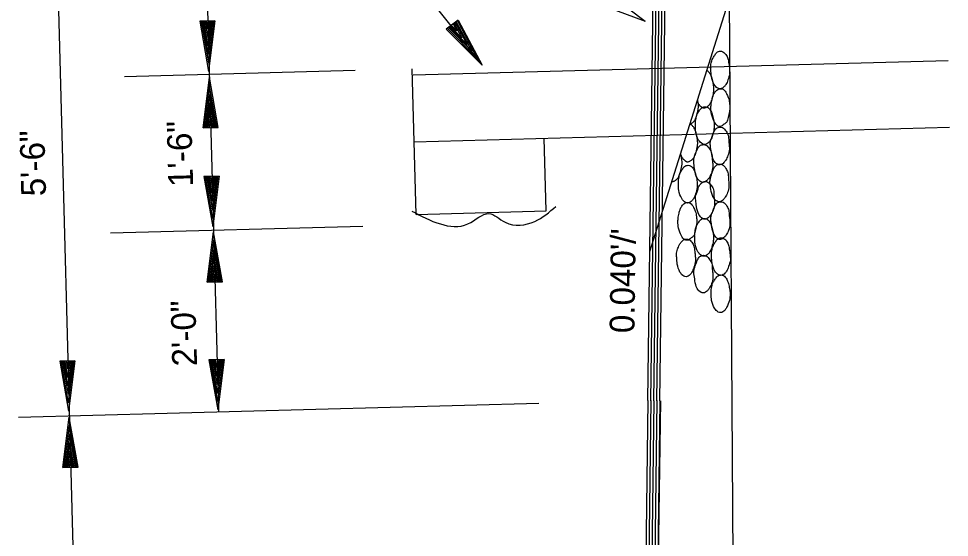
# Model space of a CAD drawing. Extents: x 1926836 to 1933254, y 596317 to 604524.
# Drawn here: x 1932874 to 1933102.1, y 600272.6 to 600399.7 of the extents above; entities that cross this region are included whole.
import ezdxf

# ---------------------------------------------------------------- set-up
doc = ezdxf.new("R2010")
doc.units = 0
doc.layers.add('Default', color=7, linetype='Continuous')

msp = doc.modelspace()

# ---------------------------------------------------------------- linework, layer by layer
at = {"layer": 'Default'}
for p, q in [((1933028.65, 600342.66), (1933087.62, 600529.6)), ((1933050.22, 600105.35), (1933047.48, 600498.79)), ((1932987.41, 600388.62), (1932933.19, 600456.49)), ((1933028.17, 600306.1), (1933029.94, 600440.85)), ((1933028.91, 600306.08), (1933030.68, 600440.83)), ((1933029.64, 600306.07), (1933031.42, 600440.83)), ((1933030.38, 600306.06), (1933032.16, 600440.81)), ((1933031.12, 600306.06), (1933032.89, 600440.81)), ((1932923, 600303.28), (1932919.41, 600436.93)), ((1932891.73, 600105.54), (1932882.86, 600435.95)), ((1933017.57, 600406.6), (1933027.52, 600399.09)), ((1933015.79, 600403.36), (1933027.52, 600399.09)), ((1932922.05, 600399.14), (1932918.34, 600399.04)), ((1932918.34, 600399.04), (1932920.51, 600386.77)), ((1932918.66, 600399.05), (1932920.46, 600388.84)), ((1932918.98, 600399.06), (1932920.4, 600390.95)), ((1932919.27, 600399.07), (1932920.34, 600393.02)), ((1932919.59, 600399.08), (1932920.29, 600395.08)), ((1932919.91, 600399.09), (1932920.23, 600397.15)), ((1932920.48, 600399.1), (1932920.23, 600397.15)), ((1932920.8, 600399.11), (1932920.29, 600395.08)), ((1932921.12, 600399.12), (1932920.34, 600393.02)), ((1932921.41, 600399.13), (1932920.4, 600390.95)), ((1932921.73, 600399.13), (1932920.46, 600388.84)), ((1932922.05, 600399.14), (1932920.51, 600386.77)), ((1932981.71, 600399.3), (1932978.76, 600397.13)), ((1932979, 600397.33), (1932986.36, 600389.95)), ((1932979.29, 600397.54), (1932985.04, 600391.71)), ((1932979.54, 600397.67), (1932983.84, 600393.34)), ((1932979.74, 600397.86), (1932982.61, 600394.98)), ((1932980.01, 600398.04), (1932981.38, 600396.66)), ((1932980.42, 600398.4), (1932981.38, 600396.66)), ((1932980.69, 600398.53), (1932982.61, 600394.98)), ((1932980.96, 600398.74), (1932983.84, 600393.34)), ((1932981.22, 600398.92), (1932985.04, 600391.71)), ((1932981.48, 600399.15), (1932986.36, 600389.95)), ((1932981.71, 600399.3), (1932987.56, 600388.3)), ((1932978.76, 600397.13), (1932987.56, 600388.3)), ((1932970.62, 600385.93), (1933101.74, 600389.44)), ((1932956.47, 600386.97), (1932899.92, 600385.45)), ((1932971.39, 600351.71), (1932970.44, 600387.35)), ((1932919.16, 600372.95), (1932920.7, 600385.32)), ((1932922.87, 600373.05), (1932920.7, 600385.32)), ((1932919.48, 600372.96), (1932920.75, 600383.26)), ((1932922.55, 600373.04), (1932920.75, 600383.26)), ((1932919.8, 600372.97), (1932920.81, 600381.14)), ((1932920.09, 600372.98), (1932920.87, 600379.08)), ((1932922.23, 600373.03), (1932920.81, 600381.14)), ((1932921.94, 600373.03), (1932920.87, 600379.08)), ((1932920.41, 600372.98), (1932920.92, 600377.01)), ((1932921.62, 600373.02), (1932920.92, 600377.01)), ((1932920.73, 600372.99), (1932920.98, 600374.94)), ((1932921.3, 600373.01), (1932920.98, 600374.94)), ((1932919.16, 600372.95), (1932922.87, 600373.05)), ((1932970.91, 600369.54), (1933102.05, 600373.06)), ((1933003.22, 600352.56), (1933002.74, 600370.4)), ((1932923.1, 600361.07), (1932919.38, 600360.97)), ((1932919.38, 600360.97), (1932921.56, 600348.7)), ((1932919.7, 600360.98), (1932921.5, 600350.76)), ((1932920.02, 600360.99), (1932921.45, 600352.88)), ((1932920.32, 600361), (1932921.39, 600354.95)), ((1932920.64, 600361), (1932921.34, 600357.01)), ((1932920.96, 600361.01), (1932921.28, 600359.08)), ((1932921.52, 600361.03), (1932921.28, 600359.08)), ((1932921.84, 600361.04), (1932921.34, 600357.01)), ((1932922.16, 600361.05), (1932921.39, 600354.95)), ((1932922.46, 600361.05), (1932921.45, 600352.88)), ((1932922.78, 600361.06), (1932921.5, 600350.76)), ((1932923.1, 600361.07), (1932921.56, 600348.7)), ((1932971.39, 600351.71), (1933003.22, 600352.56)), ((1932958.29, 600348.8), (1932896.45, 600347.14)), ((1932920.2, 600335.1), (1932921.74, 600347.47)), ((1932923.91, 600335.2), (1932921.74, 600347.47)), ((1932920.52, 600335.11), (1932921.79, 600345.41)), ((1932923.6, 600335.19), (1932921.79, 600345.41)), ((1932920.84, 600335.12), (1932921.85, 600343.29)), ((1932923.28, 600335.18), (1932921.85, 600343.29)), ((1932921.14, 600335.13), (1932921.91, 600341.23)), ((1932922.98, 600335.17), (1932921.91, 600341.23)), ((1932921.46, 600335.13), (1932921.96, 600339.16)), ((1932922.66, 600335.17), (1932921.96, 600339.16)), ((1932921.78, 600335.14), (1932922.02, 600337.09)), ((1932922.34, 600335.16), (1932922.02, 600337.09)), ((1932920.2, 600335.1), (1932923.91, 600335.2)), ((1932887.74, 600315.87), (1932884.02, 600315.77)), ((1932884.02, 600315.77), (1932886.2, 600303.5)), ((1932884.34, 600315.78), (1932886.14, 600305.56)), ((1932884.66, 600315.79), (1932886.09, 600307.68)), ((1932884.96, 600315.79), (1932886.03, 600309.74)), ((1932885.28, 600315.8), (1932885.97, 600311.81)), ((1932885.6, 600315.81), (1932885.92, 600313.87)), ((1932886.16, 600315.83), (1932885.92, 600313.87)), ((1932886.48, 600315.83), (1932885.97, 600311.81)), ((1932886.8, 600315.84), (1932886.03, 600309.74)), ((1932887.1, 600315.85), (1932886.09, 600307.68)), ((1932887.42, 600315.86), (1932886.14, 600305.56)), ((1932887.74, 600315.87), (1932886.2, 600303.5)), ((1932924.3, 600316.18), (1932920.59, 600316.09)), ((1932920.59, 600316.09), (1932922.76, 600303.81)), ((1932920.91, 600316.09), (1932922.71, 600305.88)), ((1932921.23, 600316.1), (1932922.65, 600307.99)), ((1932921.52, 600316.11), (1932922.6, 600310.06)), ((1932921.84, 600316.12), (1932922.54, 600312.13)), ((1932922.16, 600316.13), (1932922.49, 600314.19)), ((1932922.73, 600316.14), (1932922.49, 600314.19)), ((1932923.05, 600316.15), (1932922.54, 600312.13)), ((1932923.37, 600316.16), (1932922.6, 600310.06)), ((1932923.66, 600316.17), (1932922.65, 600307.99)), ((1932923.98, 600316.18), (1932922.71, 600305.88)), ((1932924.3, 600316.18), (1932922.76, 600303.81)), ((1933028.17, 600306.1), (1933026.23, 600158.37)), ((1933028.91, 600306.12), (1933026.96, 600158.39)), ((1933029.64, 600306.09), (1933027.7, 600158.36)), ((1933030.38, 600306.11), (1933028.44, 600158.38)), ((1933031.12, 600306.08), (1933029.18, 600158.35)), ((1933031.22, 600306.08), (1933029.28, 600158.45)), ((1933001.46, 600305.38), (1932873.96, 600301.96)), ((1932884.82, 600289.68), (1932886.36, 600302.05)), ((1932888.54, 600289.78), (1932886.36, 600302.05)), ((1932885.14, 600289.68), (1932886.42, 600299.98)), ((1932888.22, 600289.77), (1932886.42, 600299.98)), ((1932885.46, 600289.69), (1932886.47, 600297.87)), ((1932887.9, 600289.76), (1932886.47, 600297.87)), ((1932885.76, 600289.7), (1932886.53, 600295.8)), ((1932887.6, 600289.75), (1932886.53, 600295.8)), ((1932886.08, 600289.71), (1932886.58, 600293.73)), ((1932887.28, 600289.74), (1932886.58, 600293.73)), ((1932886.4, 600289.72), (1932886.64, 600291.67)), ((1932886.96, 600289.73), (1932886.64, 600291.67)), ((1932884.82, 600289.68), (1932888.54, 600289.78))]:
    msp.add_line(p, q, dxfattribs=at)
for points in [[(1933043.56, 600387.12), (1933043.75, 600385.5), (1933044.39, 600383.55), (1933045.3, 600382.64), (1933045.9, 600382.51), (1933046.87, 600383.02), (1933047.3, 600383.53), (1933047.76, 600384.67), (1933048.21, 600386.21), (1933048.19, 600387.05), (1933048.06, 600388.27), (1933047.82, 600389.65), (1933047.45, 600390.62), (1933046.54, 600391.58), (1933045.94, 600391.71), (1933045.07, 600391.39), (1933044.5, 600390.64), (1933044.07, 600389.89), (1933043.71, 600388.85), (1933043.58, 600388.15), (1933043.56, 600387.12)], [(1933040.25, 600379.42), (1933040.37, 600379.16), (1933040.44, 600379.03), (1933040.51, 600378.9), (1933040.71, 600378.61), (1933040.93, 600378.36), (1933041.18, 600378.14), (1933041.32, 600378.04), (1933041.48, 600377.94), (1933041.61, 600377.87), (1933041.75, 600377.82), (1933041.89, 600377.8), (1933041.95, 600377.8), (1933042.02, 600377.81), (1933042.29, 600377.89), (1933042.55, 600378.01), (1933042.8, 600378.18), (1933042.92, 600378.27), (1933043.04, 600378.38), (1933043.28, 600378.64), (1933043.47, 600378.93), (1933043.6, 600379.2), (1933043.73, 600379.47), (1933043.84, 600379.74), (1933043.93, 600380.02), (1933044.13, 600380.81), (1933044.28, 600381.61), (1933044.36, 600382.45), (1933044.35, 600382.6), (1933044.34, 600382.74), (1933044.31, 600383.04), (1933044.23, 600383.63), (1933044.17, 600383.96), (1933044.1, 600384.29), (1933044.03, 600384.62), (1933043.95, 600384.95), (1933043.86, 600385.21), (1933043.76, 600385.47), (1933043.65, 600385.72), (1933043.52, 600385.97), (1933043.37, 600386.24), (1933043.2, 600386.49), (1933042.98, 600386.72), (1933042.85, 600386.83), (1933042.78, 600386.88), (1933042.71, 600386.93), (1933042.63, 600386.98)], [(1933043.62, 600377.87), (1933043.76, 600376.25), (1933044.5, 600374.35), (1933045.31, 600373.38), (1933045.86, 600373.25), (1933046.88, 600373.82), (1933047.41, 600374.28), (1933047.87, 600375.47), (1933048.17, 600376.96), (1933048.25, 600377.79), (1933048.16, 600379.02), (1933047.88, 600380.39), (1933047.41, 600381.37), (1933046.6, 600382.38), (1933045.95, 600382.51), (1933045.08, 600382.19), (1933044.46, 600381.43), (1933044.13, 600380.69), (1933043.82, 600379.6), (1933043.69, 600378.9), (1933043.62, 600377.87)], [(1933038.47, 600373.79), (1933038.67, 600373.88), (1933038.87, 600373.99), (1933039.06, 600374.13), (1933039.24, 600374.29), (1933039.49, 600374.55), (1933039.67, 600374.84), (1933039.81, 600375.11), (1933039.93, 600375.38), (1933040.04, 600375.65), (1933040.13, 600375.94), (1933040.33, 600376.72), (1933040.49, 600377.52), (1933040.54, 600377.94), (1933040.56, 600378.15), (1933040.56, 600378.36), (1933040.52, 600378.95), (1933040.43, 600379.54), (1933040.38, 600379.84)], [(1933039.81, 600373.51), (1933039.91, 600371.89), (1933040.6, 600369.93), (1933041.56, 600368.98), (1933042.1, 600368.84), (1933043.12, 600369.41), (1933043.55, 600369.96), (1933044.01, 600371.06), (1933044.36, 600372.64), (1933044.44, 600373.48), (1933044.31, 600374.66), (1933044.03, 600375.98), (1933043.61, 600377.01), (1933042.79, 600377.97), (1933042.15, 600378.1), (1933041.27, 600377.78), (1933040.7, 600377.03), (1933040.28, 600376.33), (1933039.96, 600375.23), (1933039.83, 600374.54), (1933039.81, 600373.51)], [(1933036.16, 600366.47), (1933036.29, 600366.18), (1933036.41, 600365.94), (1933036.54, 600365.7), (1933036.73, 600365.41), (1933036.95, 600365.17), (1933037.2, 600364.95), (1933037.34, 600364.84), (1933037.5, 600364.74), (1933037.63, 600364.67), (1933037.77, 600364.62), (1933037.91, 600364.6), (1933037.98, 600364.6), (1933038.04, 600364.61), (1933038.31, 600364.69), (1933038.57, 600364.81), (1933038.82, 600364.98), (1933038.94, 600365.07), (1933039.06, 600365.18), (1933039.3, 600365.44), (1933039.49, 600365.73), (1933039.63, 600366), (1933039.75, 600366.27), (1933039.86, 600366.54), (1933039.95, 600366.83), (1933040.15, 600367.61), (1933040.3, 600368.41), (1933040.38, 600369.25), (1933040.37, 600369.4), (1933040.36, 600369.55), (1933040.34, 600369.84), (1933040.25, 600370.43), (1933040.19, 600370.76), (1933040.12, 600371.09), (1933040.05, 600371.42), (1933039.97, 600371.75), (1933039.89, 600372.01), (1933039.79, 600372.27), (1933039.67, 600372.52), (1933039.55, 600372.77), (1933039.39, 600373.05), (1933039.22, 600373.3), (1933039, 600373.53), (1933038.88, 600373.63), (1933038.73, 600373.73), (1933038.61, 600373.8), (1933038.49, 600373.84)], [(1933043.49, 600368.58), (1933043.73, 600366.87), (1933044.27, 600365.01), (1933045.24, 600364), (1933045.78, 600363.87), (1933046.8, 600364.44), (1933047.23, 600364.99), (1933047.79, 600366.14), (1933048.14, 600367.68), (1933048.12, 600368.46), (1933047.99, 600369.69), (1933047.85, 600371.11), (1933047.33, 600372.08), (1933046.47, 600373), (1933045.83, 600373.13), (1933044.95, 600372.81), (1933044.38, 600372.05), (1933044.1, 600371.36), (1933043.74, 600370.27), (1933043.51, 600369.62), (1933043.49, 600368.58)], [(1933039.42, 600364.19), (1933039.66, 600362.58), (1933040.21, 600360.67), (1933041.17, 600359.71), (1933041.71, 600359.58), (1933042.73, 600360.15), (1933043.16, 600360.7), (1933043.72, 600361.8), (1933044.07, 600363.38), (1933044.05, 600364.17), (1933043.92, 600365.4), (1933043.79, 600366.72), (1933043.26, 600367.79), (1933042.4, 600368.7), (1933041.76, 600368.83), (1933040.88, 600368.52), (1933040.31, 600367.76), (1933040.04, 600367.02), (1933039.57, 600365.97), (1933039.44, 600365.23), (1933039.42, 600364.19)], [(1933034.04, 600359.76), (1933034.08, 600359.75), (1933034.14, 600359.75), (1933034.21, 600359.76), (1933034.48, 600359.84), (1933034.74, 600359.97), (1933034.99, 600360.13), (1933035.11, 600360.23), (1933035.23, 600360.33), (1933035.47, 600360.59), (1933035.66, 600360.88), (1933035.79, 600361.15), (1933035.92, 600361.42), (1933036.03, 600361.7), (1933036.12, 600361.98), (1933036.32, 600362.77), (1933036.47, 600363.56), (1933036.53, 600363.98), (1933036.54, 600364.19), (1933036.55, 600364.4), (1933036.5, 600364.99), (1933036.46, 600365.29), (1933036.42, 600365.58), (1933036.32, 600366.1), (1933036.21, 600366.62)], [(1933035.65, 600359.18), (1933035.75, 600357.56), (1933036.49, 600355.61), (1933037.4, 600354.65), (1933037.99, 600354.51), (1933038.96, 600355.08), (1933039.39, 600355.64), (1933039.85, 600356.73), (1933040.25, 600358.32), (1933040.28, 600359.15), (1933040.15, 600360.33), (1933039.87, 600361.65), (1933039.45, 600362.68), (1933038.63, 600363.64), (1933038.04, 600363.77), (1933037.16, 600363.45), (1933036.59, 600362.7), (1933036.12, 600362), (1933035.8, 600360.9), (1933035.67, 600360.21), (1933035.65, 600359.18)], [(1933043.36, 600359.51), (1933043.61, 600357.84), (1933044.2, 600355.89), (1933045.11, 600354.93), (1933045.71, 600354.8), (1933046.67, 600355.36), (1933047.1, 600355.92), (1933047.71, 600357.06), (1933048.02, 600358.6), (1933047.99, 600359.39), (1933047.91, 600360.61), (1933047.73, 600361.99), (1933047.26, 600363.01), (1933046.35, 600363.92), (1933045.75, 600364.05), (1933044.87, 600363.73), (1933044.3, 600362.98), (1933043.98, 600362.23), (1933043.66, 600361.19), (1933043.48, 600360.54), (1933043.36, 600359.51)], [(1933039.89, 600355.25), (1933040.08, 600353.63), (1933040.68, 600351.67), (1933041.64, 600350.67), (1933042.19, 600350.53), (1933043.15, 600351.1), (1933043.58, 600351.65), (1933044.19, 600352.8), (1933044.5, 600354.34), (1933044.47, 600355.17), (1933044.34, 600356.35), (1933044.26, 600357.78), (1933043.74, 600358.75), (1933042.88, 600359.66), (1933042.23, 600359.79), (1933041.35, 600359.47), (1933040.78, 600358.77), (1933040.46, 600358.02), (1933040.14, 600356.98), (1933039.87, 600356.28), (1933039.89, 600355.25)], [(1933035.53, 600349.99), (1933035.67, 600348.37), (1933036.41, 600346.47), (1933037.23, 600345.51), (1933037.77, 600345.38), (1933038.79, 600345.95), (1933039.32, 600346.4), (1933039.78, 600347.6), (1933040.08, 600349.08), (1933040.16, 600349.92), (1933040.08, 600351.15), (1933039.79, 600352.52), (1933039.32, 600353.49), (1933038.51, 600354.5), (1933037.87, 600354.63), (1933036.99, 600354.32), (1933036.37, 600353.56), (1933036.04, 600352.81), (1933035.73, 600351.72), (1933035.6, 600351.03), (1933035.53, 600349.99)], [(1933043.62, 600350.25), (1933043.86, 600348.63), (1933044.45, 600346.68), (1933045.37, 600345.72), (1933045.96, 600345.59), (1933046.93, 600346.16), (1933047.36, 600346.71), (1933047.92, 600347.81), (1933048.27, 600349.34), (1933048.25, 600350.18), (1933048.12, 600351.41), (1933047.98, 600352.73), (1933047.51, 600353.75), (1933046.6, 600354.71), (1933046.01, 600354.84), (1933045.13, 600354.53), (1933044.56, 600353.77), (1933044.24, 600353.03), (1933043.87, 600351.93), (1933043.64, 600351.29), (1933043.62, 600350.25)], [(1932970.34, 600352.54), (1932977.34, 600349.38), (1932984.08, 600349.39), (1932989.21, 600351.94), (1932993.2, 600349.81), (1933000.46, 600350), (1933005.6, 600353.69)], [(1933039.64, 600346.14), (1933039.73, 600344.52), (1933040.42, 600342.57), (1933041.38, 600341.61), (1933041.93, 600341.48), (1933042.95, 600342.05), (1933043.37, 600342.6), (1933043.84, 600343.69), (1933044.19, 600345.28), (1933044.26, 600346.12), (1933044.13, 600347.3), (1933043.85, 600348.62), (1933043.43, 600349.64), (1933042.62, 600350.6), (1933041.97, 600350.73), (1933041.1, 600350.41), (1933040.53, 600349.66), (1933040.1, 600348.96), (1933039.79, 600347.87), (1933039.66, 600347.18), (1933039.64, 600346.14)], [(1933035.24, 600341.17), (1933035.38, 600339.55), (1933036.03, 600337.59), (1933036.99, 600336.59), (1933037.53, 600336.45), (1933038.5, 600336.97), (1933038.93, 600337.57), (1933039.44, 600338.72), (1933039.84, 600340.31), (1933039.82, 600341.14), (1933039.69, 600342.32), (1933039.51, 600343.64), (1933039.09, 600344.67), (1933038.23, 600345.53), (1933037.58, 600345.66), (1933036.7, 600345.34), (1933036.13, 600344.69), (1933035.76, 600343.99), (1933035.34, 600342.89), (1933035.21, 600342.2), (1933035.24, 600341.17)], [(1933043.73, 600341.4), (1933043.92, 600339.78), (1933044.56, 600337.83), (1933045.47, 600336.92), (1933046.07, 600336.79), (1933047.04, 600337.31), (1933047.47, 600337.81), (1933047.93, 600338.96), (1933048.38, 600340.49), (1933048.36, 600341.33), (1933048.22, 600342.56), (1933047.99, 600343.93), (1933047.62, 600344.9), (1933046.71, 600345.86), (1933046.11, 600346), (1933045.24, 600345.68), (1933044.67, 600344.92), (1933044.24, 600344.17), (1933043.88, 600343.13), (1933043.75, 600342.44), (1933043.73, 600341.4)], [(1933039.46, 600337.2), (1933039.7, 600335.49), (1933040.24, 600333.58), (1933041.21, 600332.62), (1933041.75, 600332.49), (1933042.77, 600333.01), (1933043.2, 600333.61), (1933043.76, 600334.71), (1933044.11, 600336.29), (1933044.09, 600337.08), (1933043.96, 600338.31), (1933043.82, 600339.68), (1933043.3, 600340.7), (1933042.44, 600341.57), (1933041.8, 600341.7), (1933040.92, 600341.38), (1933040.35, 600340.62), (1933040.07, 600339.93), (1933039.66, 600338.83), (1933039.48, 600338.19), (1933039.46, 600337.2)], [(1933043.68, 600332.29), (1933043.78, 600330.67), (1933044.52, 600328.72), (1933045.43, 600327.81), (1933046.02, 600327.68), (1933046.99, 600328.2), (1933047.42, 600328.8), (1933047.88, 600329.85), (1933048.28, 600331.48), (1933048.31, 600332.27), (1933048.18, 600333.5), (1933047.9, 600334.82), (1933047.48, 600335.84), (1933046.67, 600336.76), (1933046.07, 600336.89), (1933045.19, 600336.57), (1933044.62, 600335.82), (1933044.15, 600335.11), (1933043.83, 600334.02), (1933043.71, 600333.33), (1933043.68, 600332.29)]]:
    msp.add_spline(points, degree=3, dxfattribs=at)

# ---------------------------------------------------------------- texts
for s, rotation, p in [('1\'-6"', 91.5377, (1932916.74, 600358.54)), ('5\'-6"', 91.5377, (1932880.69, 600356.24)), ("0.040'/'", 89.2471, (1933024.86, 600322.6)), ('2\'-0"', 91.5377, (1932917.7, 600314.58))]:
    msp.add_text(s, height=6.075, rotation=rotation, dxfattribs=at).set_placement(p)

doc.saveas('drawing.dxf')
